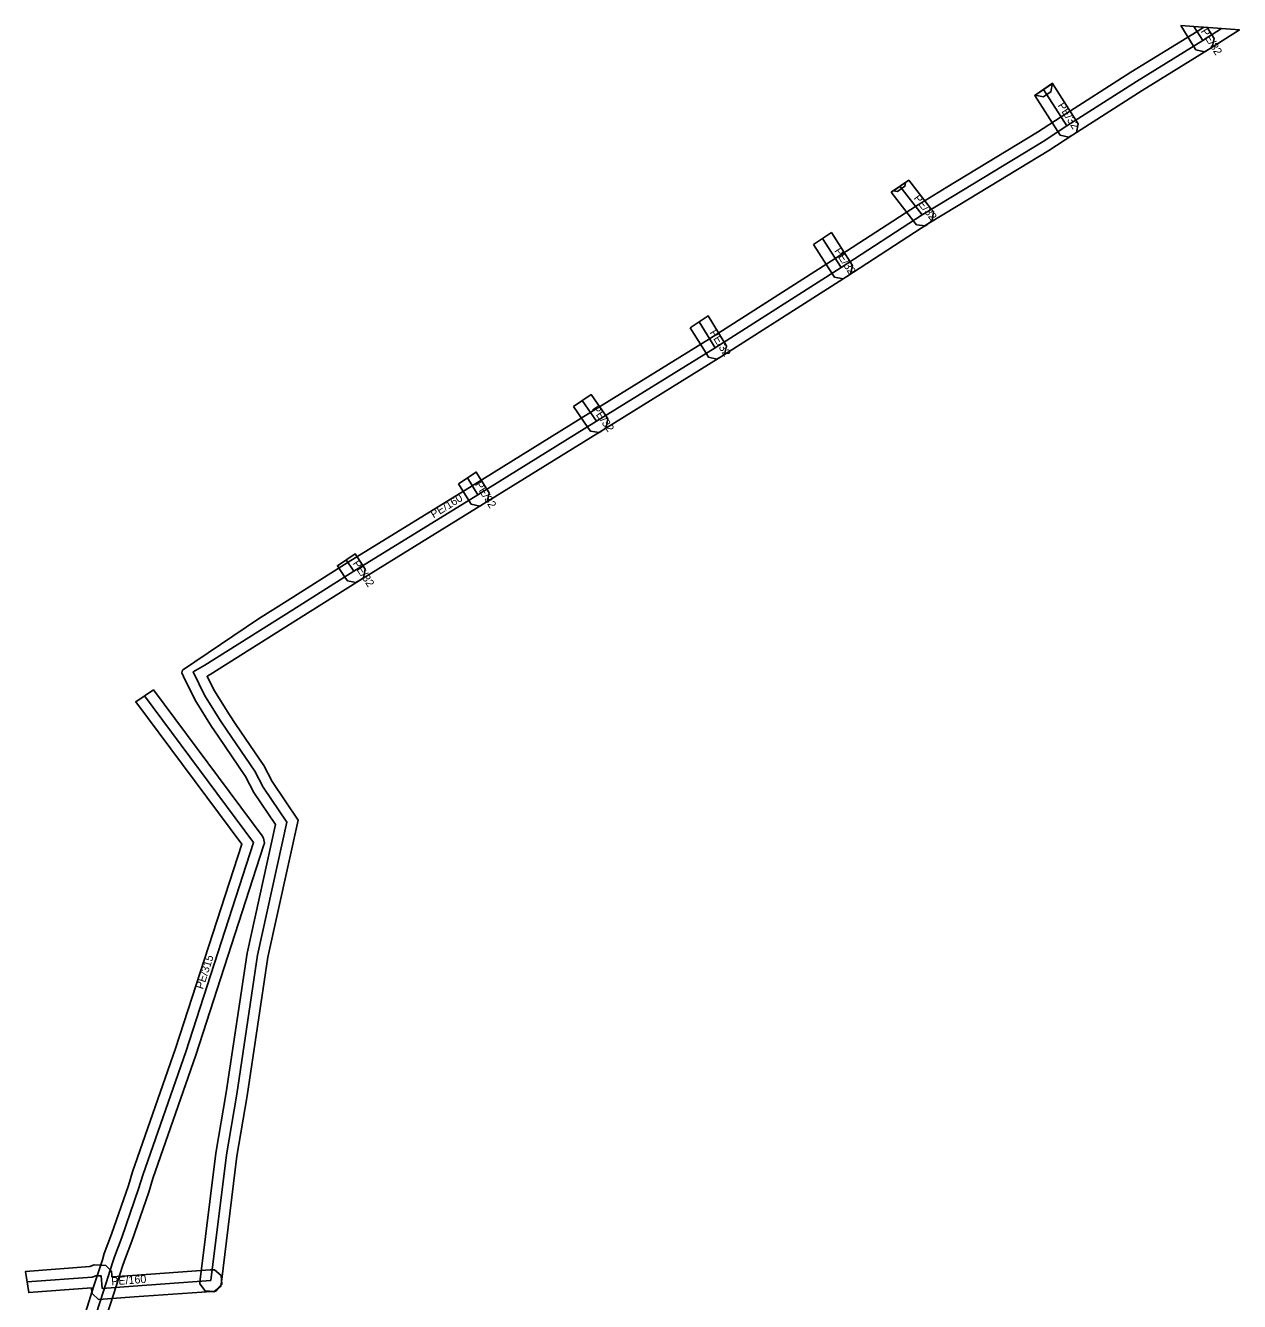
# Model space of a CAD drawing. Extents: x -492390 to -492156, y -1126301 to -1126086.
# Drawn here: x -492390 to -492276.2, y -1126205.9 to -1126086.3 of the extents above; entities that cross this region are included whole.
import ezdxf

# ---------------------------------------------------------------- set-up
doc = ezdxf.new("R2010")
doc.units = 0
for name, color, linetype in [('1', 7, 'Continuous'), ('14', 7, 'Continuous'), ('20', 7, 'Continuous'), ('24', 7, 'Continuous'), ('30', 7, 'Continuous')]:
    doc.layers.add(name, color=color, linetype=linetype)

msp = doc.modelspace()

# ---------------------------------------------------------------- linework, layer by layer
at = {"layer": '1'}
for points in [[(-492375.26, -1126146.75), (-492368.13, -1126141.95), (-492365.46, -1126140.26), (-492359.73, -1126136.63), (-492348.12, -1126129.46), (-492336.99, -1126122.58), (-492325.89, -1126115.69), (-492314.1, -1126108.18), (-492306.49, -1126103.23), (-492303.64, -1126101.5), (-492295.16, -1126096.35), (-492292.94, -1126094.9), (-492286.41, -1126090.73), (-492280.21, -1126086.9), (-492279.59, -1126086.51), (-492276.24, -1126086.76), (-492279.15, -1126088.59), (-492285.35, -1126092.43), (-492291.86, -1126096.58), (-492294.1, -1126098.05), (-492302.6, -1126103.21), (-492305.42, -1126104.92), (-492313.02, -1126109.87), (-492324.83, -1126117.38), (-492335.93, -1126124.28), (-492347.06, -1126131.16), (-492358.67, -1126138.33), (-492364.39, -1126141.95), (-492372.65, -1126147.15), (-492372.95, -1126147.32), (-492372.32, -1126148.59), (-492370.86, -1126150.93), (-492370.26, -1126151.82), (-492367.63, -1126155.69), (-492366.85, -1126157.19), (-492364.41, -1126160.8), (-492367.25, -1126173.63), (-492369.18, -1126186.62), (-492370.15, -1126192.29), (-492371.61, -1126204.06), (-492371.66, -1126204.47), (-492372.31, -1126204.98), (-492372.72, -1126204.93), (-492373.13, -1126204.88), (-492373.64, -1126204.23), (-492373.59, -1126203.82), (-492372.13, -1126191.99), (-492371.16, -1126186.3), (-492369.21, -1126173.27), (-492366.55, -1126161.2), (-492368.57, -1126158.21), (-492369.35, -1126156.71), (-492371.92, -1126152.94), (-492372.54, -1126152.03), (-492374.08, -1126149.57), (-492375.16, -1126147.35), (-492375.33, -1126146.99)], [(-492281.73, -1126086.35), (-492279.26, -1126086.53), (-492278.83, -1126087.22), (-492278.61, -1126087.57), (-492278.8, -1126088.38), (-492279.15, -1126088.6), (-492279.5, -1126088.81), (-492280.31, -1126088.63), (-492280.53, -1126088.28)], [(-492293.24, -1126096.28), (-492295.42, -1126092.89), (-492293.76, -1126091.77), (-492293.76, -1126091.78), (-492291.56, -1126095.2), (-492291.34, -1126095.55), (-492291.51, -1126096.36), (-492291.86, -1126096.58), (-492292.21, -1126096.8), (-492293.02, -1126096.63)], [(-492294.6, -1126093.02), (-492295.38, -1126092.86), (-492293.74, -1126091.76), (-492293.9, -1126092.57), (-492294.25, -1126092.79)], [(-492308.88, -1126101.97), (-492307.22, -1126100.85), (-492305.17, -1126103.46), (-492304.91, -1126103.78), (-492305.01, -1126104.61), (-492305.34, -1126104.86), (-492305.66, -1126105.12), (-492306.48, -1126105.02), (-492306.74, -1126104.7)], [(-492308.26, -1126101.9), (-492308.66, -1126101.83), (-492307.52, -1126101.06), (-492307.58, -1126101.41), (-492307.92, -1126101.65)], [(-492316.13, -1126106.86), (-492314.47, -1126105.74), (-492312.72, -1126108.49), (-492312.5, -1126108.84), (-492312.67, -1126109.65), (-492313.02, -1126109.87), (-492313.37, -1126110.09), (-492314.18, -1126109.91), (-492314.41, -1126109.56)], [(-492327.68, -1126114.66), (-492326.02, -1126113.54), (-492324.5, -1126116.01), (-492324.29, -1126116.36), (-492324.48, -1126117.17), (-492324.83, -1126117.39), (-492325.19, -1126117.6), (-492325.99, -1126117.41), (-492326.21, -1126117.06)], [(-492338.64, -1126122.05), (-492336.98, -1126120.93), (-492335.64, -1126122.85), (-492335.4, -1126123.2), (-492335.55, -1126124.01), (-492335.89, -1126124.25), (-492336.23, -1126124.49), (-492337.04, -1126124.34), (-492337.28, -1126124)], [(-492349.39, -1126129.3), (-492347.73, -1126128.18), (-492346.74, -1126129.78), (-492346.52, -1126130.13), (-492346.71, -1126130.94), (-492347.06, -1126131.16), (-492347.41, -1126131.38), (-492348.22, -1126131.19), (-492348.44, -1126130.84)], [(-492360.04, -1126138.03), (-492360.74, -1126136.96), (-492359.08, -1126135.84), (-492358.36, -1126136.93), (-492358.14, -1126137.28), (-492358.31, -1126138.09), (-492358.65, -1126138.32), (-492359, -1126138.54), (-492359.81, -1126138.37)], [(-492383.78, -1126204.62), (-492389.65, -1126205.05), (-492389.96, -1126203.07), (-492383.93, -1126202.62), (-492383.53, -1126202.47), (-492382.83, -1126202.5), (-492382.45, -1126202.52), (-492381.91, -1126203.04), (-492381.87, -1126203.41), (-492381.86, -1126203.59), (-492379.93, -1126203.45), (-492372.67, -1126202.94), (-492372.26, -1126202.91), (-492371.63, -1126203.46), (-492371.6, -1126203.87), (-492371.57, -1126204.28), (-492372.12, -1126204.91), (-492372.53, -1126204.94), (-492379.79, -1126205.45), (-492382.7, -1126205.66), (-492383.11, -1126205.69), (-492383.73, -1126205.15), (-492383.77, -1126204.75)]]:
    msp.add_lwpolyline(points, close=True, dxfattribs=at)
msp.add_lwpolyline([(-492384.32, -1126206.84), (-492383.58, -1126204.53), (-492382.76, -1126201.98), (-492382.58, -1126201.38), (-492381.89, -1126199.57), (-492380.32, -1126195.03), (-492379.93, -1126193.75), (-492375.9, -1126182.18), (-492369.71, -1126163.06), (-492379.64, -1126149.71), (-492377.98, -1126148.59), (-492367.8, -1126162.28), (-492367.65, -1126162.48), (-492367.57, -1126162.96), (-492367.65, -1126163.19), (-492374, -1126182.82), (-492378.03, -1126194.37), (-492378.42, -1126195.65), (-492380.01, -1126200.25), (-492380.68, -1126202.04), (-492380.86, -1126202.58), (-492381.68, -1126205.15), (-492382.42, -1126207.45)], dxfattribs=at)
at = {"layer": '14'}
msp.add_lwpolyline([(-492383.37, -1126207.15), (-492382.63, -1126204.84), (-492381.81, -1126202.28), (-492381.63, -1126201.71), (-492380.95, -1126199.91), (-492379.37, -1126195.34), (-492378.98, -1126194.06), (-492374.95, -1126182.5), (-492368.6, -1126162.88), (-492378.81, -1126149.15)], dxfattribs=at)
at = {"layer": '24'}
for points in [[(-492372.6, -1126203.94), (-492371.14, -1126192.14), (-492370.17, -1126186.46), (-492368.23, -1126173.45), (-492365.48, -1126161), (-492367.71, -1126157.7), (-492368.49, -1126156.2), (-492371.09, -1126152.38), (-492371.7, -1126151.48), (-492373.2, -1126149.08), (-492374.26, -1126146.91), (-492373.16, -1126146.29), (-492364.92, -1126141.1), (-492359.2, -1126137.48), (-492347.59, -1126130.31), (-492336.46, -1126123.43), (-492325.36, -1126116.53), (-492313.56, -1126109.03), (-492305.96, -1126104.08), (-492303.12, -1126102.36), (-492294.63, -1126097.2), (-492292.4, -1126095.74), (-492285.88, -1126091.58), (-492279.68, -1126087.75), (-492277.91, -1126086.63)], [(-492279.68, -1126087.75), (-492280.5, -1126086.44)], [(-492292.4, -1126095.74), (-492294.59, -1126092.33)], [(-492305.96, -1126104.08), (-492308.05, -1126101.41)], [(-492313.56, -1126109.03), (-492315.3, -1126106.3)], [(-492325.36, -1126116.53), (-492326.85, -1126114.1)], [(-492336.46, -1126123.43), (-492337.81, -1126121.49)], [(-492347.59, -1126130.31), (-492348.56, -1126128.74)], [(-492359.91, -1126136.4), (-492359.2, -1126137.48)], [(-492389.81, -1126204.06), (-492383.72, -1126203.61), (-492383.37, -1126203.48), (-492382.87, -1126203.5), (-492382.77, -1126204.66), (-492379.86, -1126204.45), (-492372.6, -1126203.94)]]:
    msp.add_lwpolyline(points, dxfattribs=at)

# ---------------------------------------------------------------- texts
at = {"layer": '20'}
msp.add_text('PE/315', height=0.75, rotation=72.0659, dxfattribs=at).set_placement((-492373.34, -1126176.69))
at = {"layer": '30'}
for s, rotation, p in [('PE/32', 301.9485, (-492279.89, -1126086.89)), ('PE/32', 302.7697, (-492293.3, -1126093.84)), ('PE/32', 308.1752, (-492306.8, -1126102.54)), ('PE/32', 302.5384, (-492314.23, -1126107.46)), ('PE/32', 301.5029, (-492325.9, -1126115.11)), ('PE/32', 304.8643, (-492336.94, -1126122.26)), ('PE/32', 301.8563, (-492347.88, -1126129.33)), ('PE/160', 31.6983, (-492351.73, -1126132.54)), ('PE/32', 303.1749, (-492359.35, -1126136.74)), ('PE/160', 4.1333, (-492381.9, -1126204.38))]:
    msp.add_text(s, height=0.75, rotation=rotation, dxfattribs=at).set_placement(p)

doc.saveas('drawing.dxf')
